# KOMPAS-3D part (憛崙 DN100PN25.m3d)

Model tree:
1. Объединить компоненты:1  (labels: СЕНС DN100PN25)

Referenced files in D:\Савин\!СЕНСОР\3D для заказчика\!Новый перечень\СЕНС\1. СЕНС\DN100\: СЕНС DN100PN25.a3d
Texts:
  СЕНС DN100PN25
  ООО НПП Сенсор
